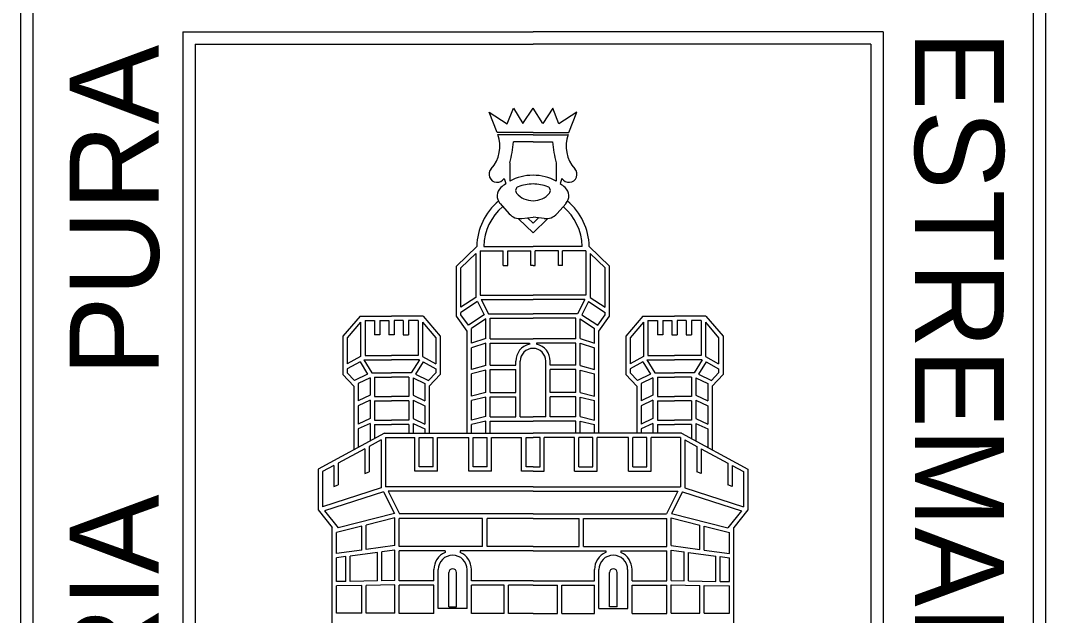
# Model space of a CAD drawing. Extents: x 0.2 to 61.3, y -17.9 to -0.8.
# Drawn here: x 17.72 to 27.72, y -12.82 to -7.03 of the extents above; entities that cross this region are included whole.
import ezdxf

# ---------------------------------------------------------------- set-up
doc = ezdxf.new("R2010")
doc.units = 0
doc.layers.add('Nivel 1', color=7, linetype='Continuous')

msp = doc.modelspace()

# ---------------------------------------------------------------- linework, layer by layer
at = {"layer": 'Nivel 1'}
for p, q in [((17.717, -5.551), (17.717, -16.25)), ((27.717, -5.551), (27.717, -16.25)), ((17.836, -5.67), (17.836, -16.25)), ((27.597, -5.67), (27.597, -16.25)), ((19.301, -7.135), (22.717, -7.135)), ((19.301, -7.135), (19.301, -15.338)), ((26.133, -7.135), (22.717, -7.135)), ((26.133, -7.135), (26.133, -15.338)), ((19.42, -7.254), (22.717, -7.254)), ((19.42, -7.254), (19.42, -15.338)), ((26.013, -7.254), (22.717, -7.254)), ((26.013, -7.254), (26.013, -15.338)), ((22.717, -8.118), (22.366, -8.118)), ((22.717, -8.138), (22.374, -8.138)), ((22.717, -8.118), (23.067, -8.118)), ((22.717, -8.138), (23.06, -8.138)), ((22.717, -8.209), (22.527, -8.209)), ((22.717, -8.209), (22.906, -8.209)), ((22.49, -8.411), (22.49, -8.591)), ((22.944, -8.411), (22.944, -8.591)), ((22.434, -8.565), (22.45, -8.615)), ((22.999, -8.565), (22.983, -8.615)), ((22.395, -8.808), (22.483, -8.908)), ((23.039, -8.808), (22.95, -8.908)), ((22.717, -9.094), (22.576, -8.959)), ((22.607, -8.955), (22.717, -8.942)), ((22.717, -9), (22.663, -8.948)), ((22.826, -8.955), (22.717, -8.942)), ((22.717, -9), (22.77, -8.948)), ((22.717, -9.094), (22.858, -8.959)), ((21.971, -9.418), (22.168, -9.228)), ((22.014, -9.436), (22.159, -9.296)), ((22.159, -9.296), (22.159, -9.723)), ((22.201, -9.269), (22.201, -9.702)), ((22.201, -9.269), (22.427, -9.269)), ((22.236, -9.227), (22.717, -9.227)), ((22.427, -9.411), (22.427, -9.269)), ((22.47, -9.411), (22.47, -9.269)), ((22.47, -9.269), (22.695, -9.269)), ((22.695, -9.411), (22.695, -9.269)), ((23.197, -9.227), (22.717, -9.227)), ((22.738, -9.411), (22.738, -9.269)), ((22.964, -9.269), (22.738, -9.269)), ((22.964, -9.411), (22.964, -9.269)), ((23.006, -9.411), (23.006, -9.269)), ((23.232, -9.269), (23.006, -9.269)), ((23.232, -9.269), (23.232, -9.702)), ((23.462, -9.418), (23.265, -9.228)), ((23.42, -9.436), (23.275, -9.296)), ((23.275, -9.296), (23.275, -9.723)), ((21.971, -9.906), (21.971, -9.418)), ((22.014, -9.819), (22.014, -9.436)), ((22.427, -9.411), (22.47, -9.411)), ((22.717, -9.411), (22.695, -9.411)), ((22.717, -9.411), (22.738, -9.411)), ((23.006, -9.411), (22.964, -9.411)), ((23.42, -9.819), (23.42, -9.436)), ((23.462, -9.906), (23.462, -9.418)), ((22.159, -9.723), (22.014, -9.819)), ((22.174, -9.764), (22.014, -9.87)), ((22.174, -9.764), (22.24, -9.892)), ((22.201, -9.702), (22.717, -9.702)), ((22.211, -9.744), (22.717, -9.744)), ((22.211, -9.744), (22.284, -9.883)), ((23.232, -9.702), (22.717, -9.702)), ((23.222, -9.744), (22.717, -9.744)), ((23.222, -9.744), (23.15, -9.883)), ((23.259, -9.764), (23.193, -9.892)), ((23.259, -9.764), (23.42, -9.87)), ((23.275, -9.723), (23.42, -9.819)), ((22.014, -9.892), (22.014, -9.87)), ((22.086, -9.995), (22.014, -9.892)), ((22.24, -9.892), (22.086, -9.995)), ((22.284, -9.883), (22.717, -9.883)), ((23.15, -9.883), (22.717, -9.883)), ((23.193, -9.892), (23.348, -9.995)), ((23.348, -9.995), (23.42, -9.892)), ((23.42, -9.892), (23.42, -9.87)), ((21.029, -9.906), (20.863, -10.102)), ((21.035, -9.965), (20.905, -10.118)), ((21.029, -9.906), (21.337, -9.906)), ((21.035, -9.965), (21.035, -10.301)), ((21.078, -9.948), (21.078, -10.29)), ((21.078, -9.948), (21.17, -9.948)), ((21.17, -9.948), (21.17, -10.087)), ((21.222, -9.948), (21.222, -10.087)), ((21.222, -9.948), (21.311, -9.948)), ((21.311, -9.948), (21.311, -10.087)), ((21.644, -9.906), (21.337, -9.906)), ((21.363, -9.948), (21.363, -10.087)), ((21.451, -9.948), (21.363, -9.948)), ((21.451, -9.948), (21.451, -10.087)), ((21.503, -9.948), (21.503, -10.087)), ((21.596, -9.948), (21.503, -9.948)), ((21.596, -9.948), (21.596, -10.29)), ((21.638, -9.965), (21.638, -10.301)), ((21.638, -9.965), (21.768, -10.118)), ((21.644, -9.906), (21.811, -10.102)), ((22.074, -10.053), (21.971, -9.906)), ((22.256, -9.932), (22.117, -10.026)), ((22.256, -10.124), (22.256, -9.932)), ((22.299, -9.925), (22.717, -9.925)), ((22.299, -10.127), (22.299, -9.925)), ((23.135, -9.925), (22.717, -9.925)), ((23.135, -10.127), (23.135, -9.925)), ((23.177, -9.932), (23.316, -10.026)), ((23.177, -10.124), (23.177, -9.932)), ((23.359, -10.053), (23.462, -9.906)), ((23.789, -9.906), (23.623, -10.102)), ((23.795, -9.965), (23.665, -10.118)), ((23.789, -9.906), (24.097, -9.906)), ((23.795, -9.965), (23.795, -10.301)), ((23.838, -9.948), (23.838, -10.29)), ((23.838, -9.948), (23.93, -9.948)), ((23.93, -9.948), (23.93, -10.087)), ((23.982, -9.948), (23.982, -10.087)), ((23.982, -9.948), (24.071, -9.948)), ((24.071, -9.948), (24.071, -10.087)), ((24.404, -9.906), (24.097, -9.906)), ((24.123, -9.948), (24.123, -10.087)), ((24.211, -9.948), (24.123, -9.948)), ((24.211, -9.948), (24.211, -10.087)), ((24.263, -9.948), (24.263, -10.087)), ((24.356, -9.948), (24.263, -9.948)), ((24.356, -9.948), (24.356, -10.29)), ((24.398, -9.965), (24.398, -10.301)), ((24.398, -9.965), (24.528, -10.118)), ((24.404, -9.906), (24.571, -10.102)), ((21.222, -10.087), (21.17, -10.087)), ((21.363, -10.087), (21.311, -10.087)), ((21.451, -10.087), (21.503, -10.087)), ((22.074, -11.047), (22.074, -10.053)), ((22.117, -10.169), (22.117, -10.026)), ((23.316, -10.169), (23.316, -10.026)), ((23.359, -11.047), (23.359, -10.053)), ((23.982, -10.087), (23.93, -10.087)), ((24.071, -10.087), (24.123, -10.087)), ((24.211, -10.087), (24.263, -10.087)), ((20.863, -10.102), (20.863, -10.476)), ((20.905, -10.118), (20.905, -10.371)), ((21.768, -10.118), (21.768, -10.371)), ((21.811, -10.102), (21.811, -10.476)), ((22.256, -10.124), (22.117, -10.169)), ((22.256, -10.168), (22.117, -10.214)), ((22.256, -10.388), (22.256, -10.168)), ((22.299, -10.127), (22.717, -10.127)), ((22.299, -10.169), (22.682, -10.169)), ((22.299, -10.384), (22.299, -10.169)), ((22.682, -10.169), (22.682, -10.181)), ((23.135, -10.127), (22.717, -10.127)), ((23.135, -10.169), (22.751, -10.169)), ((22.751, -10.169), (22.751, -10.181)), ((23.135, -10.384), (23.135, -10.169)), ((23.177, -10.124), (23.316, -10.169)), ((23.177, -10.168), (23.316, -10.214)), ((23.177, -10.388), (23.177, -10.168)), ((23.623, -10.102), (23.623, -10.476)), ((23.665, -10.118), (23.665, -10.371)), ((24.528, -10.118), (24.528, -10.371)), ((24.571, -10.102), (24.571, -10.476)), ((21.078, -10.29), (21.337, -10.29)), ((21.596, -10.29), (21.337, -10.29)), ((22.117, -10.425), (22.117, -10.214)), ((23.316, -10.425), (23.316, -10.214)), ((23.838, -10.29), (24.097, -10.29)), ((24.356, -10.29), (24.097, -10.29)), ((21.035, -10.301), (20.905, -10.371)), ((21.029, -10.353), (20.905, -10.42)), ((21.029, -10.353), (21.103, -10.472)), ((21.066, -10.333), (21.337, -10.333)), ((21.066, -10.333), (21.144, -10.459)), ((21.608, -10.333), (21.337, -10.333)), ((21.608, -10.333), (21.529, -10.459)), ((21.645, -10.353), (21.571, -10.472)), ((21.638, -10.301), (21.768, -10.371)), ((21.645, -10.353), (21.768, -10.42)), ((22.256, -10.388), (22.117, -10.425)), ((22.299, -10.384), (22.549, -10.384)), ((22.549, -10.384), (22.549, -10.345)), ((22.591, -10.886), (22.591, -10.345)), ((22.842, -10.886), (22.842, -10.345)), ((22.885, -10.384), (22.885, -10.345)), ((23.135, -10.384), (22.885, -10.384)), ((23.177, -10.388), (23.316, -10.425)), ((23.795, -10.301), (23.665, -10.371)), ((23.789, -10.353), (23.665, -10.42)), ((23.789, -10.353), (23.862, -10.472)), ((23.826, -10.333), (24.097, -10.333)), ((23.826, -10.333), (23.904, -10.459)), ((24.367, -10.333), (24.097, -10.333)), ((24.367, -10.333), (24.289, -10.459)), ((24.405, -10.353), (24.331, -10.472)), ((24.398, -10.301), (24.528, -10.371)), ((24.405, -10.353), (24.528, -10.42)), ((20.969, -10.589), (20.863, -10.476)), ((20.905, -10.42), (20.905, -10.459)), ((20.976, -10.534), (20.905, -10.459)), ((21.103, -10.472), (20.976, -10.534)), ((21.144, -10.459), (21.337, -10.459)), ((21.529, -10.459), (21.337, -10.459)), ((21.571, -10.472), (21.697, -10.534)), ((21.697, -10.534), (21.768, -10.459)), ((21.704, -10.589), (21.811, -10.476)), ((21.768, -10.42), (21.768, -10.459)), ((22.256, -10.432), (22.117, -10.469)), ((22.117, -10.685), (22.117, -10.469)), ((22.256, -10.651), (22.256, -10.432)), ((22.299, -10.427), (22.549, -10.427)), ((22.299, -10.651), (22.299, -10.427)), ((22.549, -10.651), (22.549, -10.427)), ((23.135, -10.427), (22.885, -10.427)), ((22.885, -10.651), (22.885, -10.427)), ((23.135, -10.651), (23.135, -10.427)), ((23.177, -10.432), (23.316, -10.469)), ((23.177, -10.651), (23.177, -10.432)), ((23.316, -10.685), (23.316, -10.469)), ((23.729, -10.589), (23.623, -10.476)), ((23.665, -10.42), (23.665, -10.459)), ((23.736, -10.534), (23.665, -10.459)), ((23.862, -10.472), (23.736, -10.534)), ((23.904, -10.459), (24.097, -10.459)), ((24.289, -10.459), (24.097, -10.459)), ((24.331, -10.472), (24.457, -10.534)), ((24.457, -10.534), (24.528, -10.459)), ((24.464, -10.589), (24.571, -10.476)), ((24.528, -10.42), (24.528, -10.459)), ((20.969, -10.589), (20.969, -11.208)), ((21.127, -10.507), (21.012, -10.564)), ((21.012, -10.564), (21.012, -10.732)), ((21.127, -10.507), (21.127, -10.677)), ((21.17, -10.501), (21.337, -10.501)), ((21.17, -10.501), (21.17, -10.69)), ((21.504, -10.501), (21.337, -10.501)), ((21.504, -10.501), (21.504, -10.69)), ((21.546, -10.507), (21.546, -10.677)), ((21.546, -10.507), (21.661, -10.564)), ((21.661, -10.564), (21.661, -10.732)), ((21.704, -10.589), (21.704, -11.046)), ((23.729, -10.589), (23.729, -11.046)), ((23.887, -10.507), (23.772, -10.564)), ((23.772, -10.564), (23.772, -10.732)), ((23.887, -10.507), (23.887, -10.677)), ((23.93, -10.501), (24.097, -10.501)), ((23.93, -10.501), (23.93, -10.69)), ((24.264, -10.501), (24.097, -10.501)), ((24.264, -10.501), (24.264, -10.69)), ((24.306, -10.507), (24.306, -10.677)), ((24.306, -10.507), (24.421, -10.564)), ((24.421, -10.564), (24.421, -10.732)), ((24.464, -10.589), (24.464, -11.208)), ((21.127, -10.677), (21.012, -10.732)), ((21.17, -10.69), (21.337, -10.69)), ((21.504, -10.69), (21.337, -10.69)), ((21.546, -10.677), (21.661, -10.732)), ((22.256, -10.651), (22.117, -10.685)), ((22.256, -10.695), (22.117, -10.729)), ((22.256, -10.885), (22.256, -10.695)), ((22.299, -10.651), (22.549, -10.651)), ((22.299, -10.694), (22.549, -10.694)), ((22.299, -10.886), (22.299, -10.694)), ((22.549, -10.886), (22.549, -10.694)), ((23.135, -10.651), (22.885, -10.651)), ((23.135, -10.694), (22.885, -10.694)), ((22.885, -10.886), (22.885, -10.694)), ((23.135, -10.886), (23.135, -10.694)), ((23.177, -10.651), (23.316, -10.685)), ((23.177, -10.695), (23.316, -10.729)), ((23.177, -10.885), (23.177, -10.695)), ((23.887, -10.677), (23.772, -10.732)), ((23.93, -10.69), (24.097, -10.69)), ((24.264, -10.69), (24.097, -10.69)), ((24.306, -10.677), (24.421, -10.732)), ((21.127, -10.724), (21.012, -10.779)), ((21.012, -10.779), (21.012, -10.959)), ((21.127, -10.724), (21.127, -10.904)), ((21.17, -10.733), (21.337, -10.733)), ((21.17, -10.733), (21.17, -10.92)), ((21.504, -10.733), (21.337, -10.733)), ((21.504, -10.733), (21.504, -10.92)), ((21.546, -10.724), (21.661, -10.779)), ((21.546, -10.724), (21.546, -10.904)), ((21.661, -10.779), (21.661, -10.959)), ((22.117, -10.919), (22.117, -10.729)), ((23.316, -10.919), (23.316, -10.729)), ((23.887, -10.724), (23.772, -10.779)), ((23.772, -10.779), (23.772, -10.959)), ((23.887, -10.724), (23.887, -10.904)), ((23.93, -10.733), (24.097, -10.733)), ((23.93, -10.733), (23.93, -10.92)), ((24.264, -10.733), (24.097, -10.733)), ((24.264, -10.733), (24.264, -10.92)), ((24.306, -10.724), (24.421, -10.779)), ((24.306, -10.724), (24.306, -10.904)), ((24.421, -10.779), (24.421, -10.959)), ((22.256, -10.885), (22.117, -10.919)), ((22.299, -10.886), (22.549, -10.886)), ((22.591, -10.886), (22.717, -10.886)), ((22.842, -10.886), (22.717, -10.886)), ((23.135, -10.886), (22.885, -10.886)), ((23.177, -10.885), (23.316, -10.919)), ((21.127, -10.904), (21.012, -10.959)), ((21.127, -10.951), (21.012, -11.006)), ((21.127, -10.951), (21.127, -11.122)), ((21.17, -10.92), (21.337, -10.92)), ((21.17, -10.963), (21.337, -10.963)), ((21.17, -10.963), (21.17, -11.099)), ((21.504, -10.92), (21.337, -10.92)), ((21.504, -10.963), (21.337, -10.963)), ((21.504, -10.963), (21.504, -11.046)), ((21.546, -10.904), (21.661, -10.959)), ((21.546, -10.951), (21.661, -11.006)), ((21.546, -10.951), (21.546, -11.046)), ((22.256, -10.929), (22.117, -10.962)), ((22.117, -11.047), (22.117, -10.962)), ((22.256, -11.046), (22.256, -10.929)), ((22.299, -10.929), (22.717, -10.929)), ((22.299, -11.046), (22.299, -10.929)), ((23.135, -10.929), (22.717, -10.929)), ((23.135, -11.046), (23.135, -10.929)), ((23.177, -10.929), (23.316, -10.962)), ((23.177, -11.046), (23.177, -10.929)), ((23.316, -11.047), (23.316, -10.962)), ((23.887, -10.904), (23.772, -10.959)), ((23.887, -10.951), (23.772, -11.006)), ((23.887, -10.951), (23.887, -11.046)), ((23.93, -10.92), (24.097, -10.92)), ((23.93, -10.963), (24.097, -10.963)), ((23.93, -10.963), (23.93, -11.046)), ((24.264, -10.92), (24.097, -10.92)), ((24.264, -10.963), (24.097, -10.963)), ((24.264, -10.963), (24.264, -11.099)), ((24.306, -10.904), (24.421, -10.959)), ((24.306, -10.951), (24.421, -11.006)), ((24.306, -10.951), (24.306, -11.122)), ((21.267, -11.046), (20.622, -11.396)), ((21.012, -11.006), (21.012, -11.185)), ((21.267, -11.046), (22.717, -11.046)), ((21.277, -11.089), (21.277, -11.57)), ((21.277, -11.089), (21.563, -11.089)), ((21.563, -11.416), (21.563, -11.089)), ((21.606, -11.374), (21.606, -11.089)), ((21.606, -11.089), (21.742, -11.089)), ((21.661, -11.006), (21.661, -11.046)), ((21.742, -11.374), (21.742, -11.089)), ((21.784, -11.416), (21.784, -11.089)), ((21.784, -11.089), (22.09, -11.089)), ((22.09, -11.416), (22.09, -11.089)), ((22.132, -11.374), (22.132, -11.089)), ((22.132, -11.089), (22.268, -11.089)), ((22.268, -11.374), (22.268, -11.089)), ((22.311, -11.089), (22.606, -11.089)), ((22.311, -11.416), (22.311, -11.089)), ((22.606, -11.416), (22.606, -11.089)), ((22.649, -11.374), (22.649, -11.089)), ((22.649, -11.089), (22.717, -11.089)), ((24.166, -11.046), (22.717, -11.046)), ((22.785, -11.089), (22.717, -11.089)), ((22.785, -11.374), (22.785, -11.089)), ((23.122, -11.089), (22.827, -11.089)), ((22.827, -11.416), (22.827, -11.089)), ((23.122, -11.416), (23.122, -11.089)), ((23.165, -11.374), (23.165, -11.089)), ((23.301, -11.089), (23.165, -11.089)), ((23.301, -11.374), (23.301, -11.089)), ((23.649, -11.089), (23.344, -11.089)), ((23.344, -11.416), (23.344, -11.089)), ((23.649, -11.416), (23.649, -11.089)), ((23.692, -11.374), (23.692, -11.089)), ((23.828, -11.089), (23.692, -11.089)), ((23.772, -11.006), (23.772, -11.046)), ((23.828, -11.374), (23.828, -11.089)), ((23.87, -11.416), (23.87, -11.089)), ((24.156, -11.089), (23.87, -11.089)), ((24.156, -11.089), (24.156, -11.57)), ((24.166, -11.046), (24.812, -11.396)), ((24.421, -11.006), (24.421, -11.185)), ((21.077, -11.198), (20.816, -11.339)), ((21.077, -11.198), (21.077, -11.441)), ((21.234, -11.113), (21.119, -11.175)), ((21.119, -11.175), (21.119, -11.423)), ((21.234, -11.113), (21.234, -11.58)), ((24.199, -11.113), (24.199, -11.58)), ((24.199, -11.113), (24.314, -11.175)), ((24.314, -11.175), (24.314, -11.423)), ((24.357, -11.198), (24.357, -11.441)), ((24.357, -11.198), (24.617, -11.339)), ((20.622, -11.396), (20.622, -11.795)), ((20.773, -11.362), (20.664, -11.421)), ((20.773, -11.362), (20.773, -11.567)), ((20.816, -11.339), (20.816, -11.55)), ((21.742, -11.374), (21.606, -11.374)), ((22.268, -11.374), (22.132, -11.374)), ((22.717, -11.374), (22.649, -11.374)), ((22.717, -11.374), (22.785, -11.374)), ((23.165, -11.374), (23.301, -11.374)), ((23.692, -11.374), (23.828, -11.374)), ((24.617, -11.339), (24.617, -11.55)), ((24.66, -11.362), (24.66, -11.567)), ((24.66, -11.362), (24.769, -11.421)), ((24.812, -11.396), (24.812, -11.795)), ((20.664, -11.421), (20.664, -11.763)), ((21.077, -11.441), (21.119, -11.423)), ((21.784, -11.416), (21.563, -11.416)), ((22.311, -11.416), (22.09, -11.416)), ((22.717, -11.416), (22.606, -11.416)), ((22.717, -11.416), (22.827, -11.416)), ((23.122, -11.416), (23.344, -11.416)), ((23.649, -11.416), (23.87, -11.416)), ((24.357, -11.441), (24.314, -11.423)), ((24.769, -11.421), (24.769, -11.763)), ((21.234, -11.58), (20.664, -11.763)), ((20.773, -11.567), (20.816, -11.55)), ((22.717, -11.57), (21.277, -11.57)), ((22.717, -11.57), (24.156, -11.57)), ((24.199, -11.58), (24.769, -11.763)), ((24.66, -11.567), (24.617, -11.55)), ((21.258, -11.617), (20.682, -11.802)), ((21.258, -11.617), (21.365, -11.829)), ((22.717, -11.613), (21.303, -11.613)), ((21.303, -11.613), (21.415, -11.834)), ((22.717, -11.613), (24.13, -11.613)), ((24.13, -11.613), (24.018, -11.834)), ((24.176, -11.617), (24.068, -11.829)), ((24.176, -11.617), (24.752, -11.802)), ((20.622, -11.795), (20.758, -11.965)), ((24.812, -11.795), (24.676, -11.965)), ((20.682, -11.802), (20.815, -11.968)), ((21.365, -11.829), (20.815, -11.968)), ((21.368, -11.872), (21.09, -11.942)), ((21.368, -12.143), (21.368, -11.872)), ((22.225, -11.877), (21.411, -11.877)), ((21.411, -12.151), (21.411, -11.877)), ((22.717, -11.834), (21.415, -11.834)), ((22.225, -12.151), (22.225, -11.877)), ((22.717, -11.877), (22.268, -11.877)), ((22.268, -12.151), (22.268, -11.877)), ((22.717, -11.834), (24.018, -11.834)), ((22.717, -11.877), (23.166, -11.877)), ((23.166, -12.151), (23.166, -11.877)), ((23.208, -11.877), (24.022, -11.877)), ((23.208, -12.151), (23.208, -11.877)), ((24.022, -12.151), (24.022, -11.877)), ((24.065, -12.143), (24.065, -11.872)), ((24.065, -11.872), (24.343, -11.942)), ((24.068, -11.829), (24.618, -11.968)), ((24.752, -11.802), (24.618, -11.968)), ((20.758, -13.544), (20.758, -11.965)), ((21.047, -11.953), (20.8, -12.016)), ((21.047, -12.186), (21.047, -11.953)), ((21.09, -12.18), (21.09, -11.942)), ((24.343, -12.18), (24.343, -11.942)), ((24.386, -12.186), (24.386, -11.953)), ((24.386, -11.953), (24.633, -12.016)), ((24.676, -13.544), (24.676, -11.965)), ((20.8, -12.22), (20.8, -12.016)), ((24.633, -12.22), (24.633, -12.016)), ((21.047, -12.186), (20.8, -12.22)), ((21.368, -12.143), (21.09, -12.18)), ((21.368, -12.186), (21.242, -12.203)), ((21.368, -12.483), (21.368, -12.186)), ((22.225, -12.151), (21.411, -12.151)), ((21.859, -12.193), (21.411, -12.193)), ((21.411, -12.486), (21.411, -12.193)), ((21.859, -12.193), (21.859, -12.209)), ((22.717, -12.193), (22.007, -12.193)), ((22.007, -12.193), (22.007, -12.209)), ((22.717, -12.151), (22.268, -12.151)), ((22.717, -12.151), (23.166, -12.151)), ((22.717, -12.193), (23.426, -12.193)), ((23.208, -12.151), (24.022, -12.151)), ((23.426, -12.193), (23.426, -12.209)), ((23.575, -12.193), (24.022, -12.193)), ((23.575, -12.193), (23.575, -12.209)), ((24.022, -12.486), (24.022, -12.193)), ((24.065, -12.143), (24.343, -12.18)), ((24.065, -12.483), (24.065, -12.186)), ((24.065, -12.186), (24.192, -12.203)), ((24.386, -12.186), (24.633, -12.22)), ((20.892, -12.25), (20.8, -12.262)), ((20.8, -12.493), (20.8, -12.262)), ((20.892, -12.491), (20.892, -12.25)), ((21.199, -12.209), (20.934, -12.244)), ((20.934, -12.491), (20.934, -12.244)), ((21.199, -12.486), (21.199, -12.209)), ((21.242, -12.485), (21.242, -12.203)), ((24.192, -12.485), (24.192, -12.203)), ((24.234, -12.486), (24.234, -12.209)), ((24.234, -12.209), (24.499, -12.244)), ((24.499, -12.491), (24.499, -12.244)), ((24.542, -12.491), (24.542, -12.25)), ((24.542, -12.25), (24.633, -12.262)), ((24.633, -12.493), (24.633, -12.262)), ((21.75, -12.486), (21.75, -12.376)), ((21.793, -12.755), (21.793, -12.376)), ((22.073, -12.755), (22.073, -12.376)), ((22.116, -12.486), (22.116, -12.376)), ((23.318, -12.486), (23.318, -12.376)), ((23.36, -12.755), (23.36, -12.376)), ((23.641, -12.755), (23.641, -12.376)), ((23.683, -12.486), (23.683, -12.376)), ((20.892, -12.491), (20.8, -12.493)), ((21.199, -12.486), (20.934, -12.491)), ((21.368, -12.483), (21.242, -12.485)), ((21.75, -12.486), (21.411, -12.486)), ((21.895, -12.739), (21.895, -12.406)), ((21.971, -12.739), (21.971, -12.406)), ((22.717, -12.486), (22.116, -12.486)), ((22.717, -12.486), (23.318, -12.486)), ((23.463, -12.739), (23.463, -12.406)), ((23.538, -12.739), (23.538, -12.406)), ((23.683, -12.486), (24.022, -12.486)), ((24.065, -12.483), (24.192, -12.485)), ((24.234, -12.486), (24.499, -12.491)), ((24.542, -12.491), (24.633, -12.493)), ((21.047, -12.531), (20.8, -12.536)), ((20.8, -12.801), (20.8, -12.536)), ((21.047, -12.801), (21.047, -12.531)), ((21.368, -12.525), (21.09, -12.53)), ((21.09, -12.801), (21.09, -12.53)), ((21.368, -12.801), (21.368, -12.525)), ((21.75, -12.529), (21.411, -12.529)), ((21.411, -12.803), (21.411, -12.529)), ((21.75, -12.803), (21.75, -12.529)), ((22.436, -12.529), (22.116, -12.529)), ((22.116, -12.803), (22.116, -12.529)), ((22.436, -12.803), (22.436, -12.529)), ((22.717, -12.529), (22.479, -12.529)), ((22.479, -12.803), (22.479, -12.529)), ((22.717, -12.529), (22.955, -12.529)), ((22.955, -12.803), (22.955, -12.529)), ((22.997, -12.529), (23.318, -12.529)), ((22.997, -12.803), (22.997, -12.529)), ((23.318, -12.803), (23.318, -12.529)), ((23.683, -12.529), (24.022, -12.529)), ((23.683, -12.803), (23.683, -12.529)), ((24.022, -12.803), (24.022, -12.529)), ((24.065, -12.801), (24.065, -12.525)), ((24.065, -12.525), (24.343, -12.53)), ((24.343, -12.801), (24.343, -12.53)), ((24.386, -12.531), (24.633, -12.536)), ((24.386, -12.801), (24.386, -12.531)), ((24.633, -12.801), (24.633, -12.536)), ((22.073, -12.755), (21.793, -12.755)), ((21.895, -12.739), (21.971, -12.739)), ((23.36, -12.755), (23.641, -12.755)), ((23.538, -12.739), (23.463, -12.739)), ((21.047, -12.801), (20.8, -12.801)), ((21.368, -12.801), (21.09, -12.801)), ((21.75, -12.803), (21.411, -12.803)), ((22.436, -12.803), (22.116, -12.803)), ((22.717, -12.803), (22.479, -12.803)), ((22.717, -12.803), (22.955, -12.803)), ((22.997, -12.803), (23.318, -12.803)), ((23.683, -12.803), (24.022, -12.803)), ((24.065, -12.801), (24.343, -12.801)), ((24.386, -12.801), (24.633, -12.801))]:
    msp.add_line(p, q, dxfattribs=at)
for points in [[(22.366, -8.118), (22.288, -7.919), (22.464, -8.031), (22.525, -7.878), (22.619, -8.029), (22.717, -7.88)], [(23.067, -8.118), (23.145, -7.919), (22.969, -8.031), (22.909, -7.878), (22.814, -8.029), (22.717, -7.88)]]:
    msp.add_lwpolyline(points, dxfattribs=at)
for centre, radius, start, end in [((22.069, -8.25), 0.325, 317.4659, 20.2554), ((23.364, -8.25), 0.325, 159.7446, 222.5341), ((21.39, -8.105), 1.142, 344.4358, 354.7844), ((24.044, -8.105), 1.142, 185.2156, 195.5642), ((22.367, -8.523), 0.0791, 137.4659, 328.4974), ((23.067, -8.523), 0.0791, 211.5026, 42.5341), ((22.717, -9), 0.467, 90, 119.0445), ((22.717, -9), 0.467, 60.9555, 90), ((22.477, -8.734), 0.11, 132.0862, 221.577), ((22.717, -9), 0.467, 124.7109, 132.0862), ((22.586, -8.682), 0.0392, 112.3199, 220.2347), ((22.717, -9), 0.382, 90, 112.3199), ((22.717, -9), 0.382, 67.6801, 90), ((22.847, -8.682), 0.0392, 319.7653, 67.6801), ((22.717, -9), 0.467, 47.9138, 55.2891), ((22.956, -8.734), 0.11, 318.423, 47.9138), ((22.758, -9.238), 0.59, 129.8743, 179.0027), ((22.717, -8.572), 0.21, 220.2347, 270), ((22.717, -8.572), 0.21, 270, 319.7653), ((22.675, -9.238), 0.59, 0.9973, 50.1257), ((22.758, -9.238), 0.522, 130.0091, 178.7136), ((22.675, -9.238), 0.522, 1.2864, 49.9909), ((22.591, -8.812), 0.144, 221.577, 276.6131), ((22.843, -8.812), 0.144, 263.3869, 318.423), ((22.717, -10.345), 0.168, 101.9677, 180), ((22.717, -10.345), 0.168, 0, 78.0323), ((22.717, -10.345), 0.125, 90, 180), ((22.717, -10.345), 0.125, 0, 90), ((21.933, -12.376), 0.183, 114.0127, 180), ((21.933, -12.376), 0.14, 0, 180), ((21.933, -12.376), 0.183, 360, 65.9873), ((23.5, -12.376), 0.183, 114.0127, 180), ((23.5, -12.376), 0.14, 0, 180), ((23.5, -12.376), 0.183, 0, 65.9873), ((21.933, -12.406), 0.0376, 0, 180), ((23.5, -12.406), 0.0376, 0, 180)]:
    msp.add_arc(centre, radius, start, end, dxfattribs=at)

# ---------------------------------------------------------------- texts
for s, height, rotation, p in [('PURA', 0.8686, 90, (19.066, -10.489)), ('ESTREMADURA ', 0.86862, 270, (26.442, -7.123)), ('SORIA', 0.8686, 90, (19.066, -15.258))]:
    msp.add_text(s, height=height, rotation=rotation, dxfattribs=at).set_placement(p)

doc.saveas('drawing.dxf')
